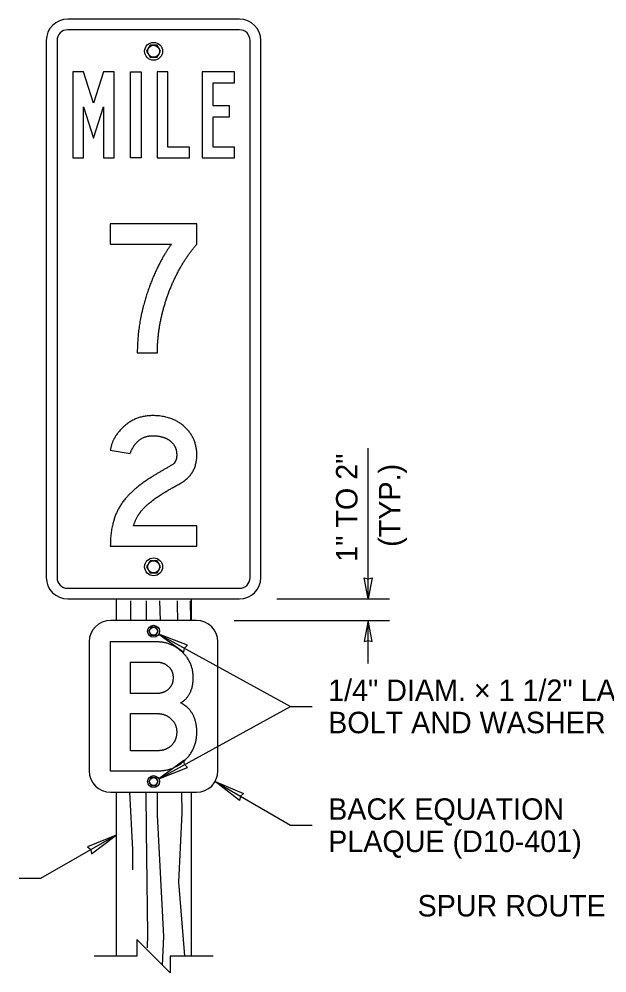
# Model space of a CAD drawing. Extents: x 99862 to 103151, y 100000 to 102076.
# Drawn here: x 101511 to 101950, y 100780 to 101491 of the extents above; entities that cross this region are included whole.
import ezdxf

# ---------------------------------------------------------------- set-up
doc = ezdxf.new("R2010")
doc.units = 0
for name, color, linetype in [('Level 11', 7, 'Continuous'), ('Level 15', 7, 'Continuous'), ('Level 2', 7, 'Continuous'), ('Level 20', 7, 'Continuous')]:
    doc.layers.add(name, color=color, linetype=linetype)

msp = doc.modelspace()

# ---------------------------------------------------------------- linework, layer by layer
at = {"layer": 'Level 11'}
for points in [[(101594.56, 101042.64), (101594.67, 101057.15)], [(101606.41, 101042.64), (101606.25, 101057.15)], [(101616.72, 101042.64), (101616.2, 101057.15)], [(101629.79, 101042.64), (101629.53, 101054.59), (101629.5, 101057.15)], [(101639.38, 101042.64), (101639.24, 101057.15)], [(101596.08, 100856.93), (101596.2, 100872.08), (101593.93, 100914.64)], [(101607.06, 100798.85), (101607.29, 100809), (101606.43, 100886.2), (101605.97, 100914.64)], [(101618.21, 100785.89), (101619.29, 100807.11), (101614.65, 100897.5), (101614.65, 100914.64)], [(101634.75, 100792.48), (101634.8, 100792.93), (101630.38, 100847.6), (101632.94, 100899.38), (101632.61, 100914.64)]]:
    msp.add_lwpolyline(points, dxfattribs=at)
at = {"layer": 'Level 15'}
for p, q in [((101771.62, 101058.64), (101771.62, 101170.99)), ((101583.62, 101058.64), (101583.62, 101042.64)), ((101639.62, 101058.64), (101639.62, 101042.64)), ((101703.62, 101058.64), (101787.62, 101058.64)), ((101671.62, 101042.64), (101787.62, 101042.64)), ((101771.62, 101010.64), (101771.62, 101042.64)), ((101615.52, 101032.5), (101713.77, 100978.64)), ((101615.52, 100924.77), (101713.77, 100978.64)), ((101713.77, 100978.64), (101729.77, 100978.64)), ((101657.47, 100922.64), (101713.77, 100890.14)), ((101583.62, 100914.64), (101583.62, 100792.48)), ((101639.62, 100914.64), (101639.62, 100792.48)), ((101713.77, 100890.14), (101729.77, 100890.14)), ((101583.62, 100882.82), (101527.33, 100850.32)), ((101527.33, 100850.32), (101511.33, 100850.32))]:
    msp.add_line(p, q, dxfattribs=at)
for points in [[(101771.62, 101058.64), (101768.54, 101074.36), (101771.62, 101073.63), (101774.7, 101074.36)], [(101771.62, 101042.64), (101768.54, 101026.91), (101771.62, 101027.64), (101774.7, 101026.91)], [(101615.52, 101032.5), (101634.1, 101018.91), (101634.61, 101022.03), (101636.97, 101024.14)], [(101615.52, 100924.77), (101636.97, 100933.13), (101634.61, 100935.24), (101634.1, 100938.37)], [(101657.48, 100922.64), (101678.74, 100913.81), (101676.33, 100911.75), (101675.75, 100908.64)], [(101583.62, 100882.82), (101562.36, 100873.99), (101564.76, 100871.93), (101565.34, 100868.82)]]:
    msp.add_lwpolyline(points, close=True, dxfattribs=at)
msp.add_lwpolyline([(101656.01, 100792.48), (101624.01, 100792.48), (101624.01, 100780.09), (101599.23, 100804.87), (101599.23, 100792.48), (101567.23, 100792.48)], dxfattribs=at)
at = {"layer": 'Level 2'}
for p, q in [((101675.62, 101482.64), (101547.62, 101482.64)), ((101539.62, 101474.64), (101539.62, 101074.64)), ((101683.62, 101074.64), (101683.62, 101474.64)), ((101547.62, 101066.64), (101675.62, 101066.64))]:
    msp.add_line(p, q, dxfattribs=at)
for points in [[(101675.62, 101490.64), (101547.62, 101490.64)], [(101531.62, 101474.64), (101531.62, 101074.64)], [(101691.62, 101074.64), (101691.62, 101474.64)], [(101559.3, 101451.24), (101551.3, 101451.24), (101551.3, 101387.24), (101559.3, 101387.24), (101559.3, 101425.26)], [(101574.34, 101451.24), (101566.82, 101428), (101559.3, 101451.24)], [(101574.34, 101425.26), (101574.34, 101387.24), (101582.34, 101387.24), (101582.34, 101451.24), (101574.34, 101451.24)], [(101638.34, 101395.24), (101622.34, 101395.24), (101622.34, 101451.24), (101614.34, 101451.24), (101614.34, 101387.24), (101638.34, 101387.24), (101638.34, 101395.24)], [(101559.3, 101425.26), (101566.82, 101402.03), (101574.34, 101425.26)], [(101643.87, 101323.04), (101643.87, 101338.04), (101579.37, 101338.04), (101579.37, 101323.04), (101624.97, 101323.04)], [(101599.47, 101242.04), (101614.47, 101242.04)], [(101579.37, 101169.44), (101594.07, 101167.04)], [(101643.87, 101098.04), (101643.87, 101113.04), (101596.62, 101113.04)], [(101579.37, 101098.04), (101643.87, 101098.04)], [(101547.62, 101058.64), (101675.62, 101058.64)], [(101643.62, 101042.64), (101579.62, 101042.64)], [(101563.62, 101026.64), (101563.62, 100930.64)], [(101614.47, 101026.64), (101579.37, 101026.64), (101579.37, 100930.64), (101615.07, 100930.64)], [(101659.62, 100930.64), (101659.62, 101026.64)], [(101614.47, 100988.24), (101594.37, 100988.24), (101594.37, 101011.64), (101614.47, 101011.64)], [(101615.07, 100945.64), (101594.37, 100945.64), (101594.37, 100973.24), (101615.07, 100973.24)], [(101579.62, 100914.64), (101643.62, 100914.64)]]:
    msp.add_lwpolyline(points, dxfattribs=at)
for points in [[(101614.22, 101471.14), (101609.02, 101471.14), (101606.42, 101466.64), (101609.02, 101462.14), (101614.22, 101462.14), (101616.82, 101466.64)], [(101614.22, 101471.14), (101609.02, 101471.14), (101606.42, 101466.64), (101609.02, 101462.14), (101614.22, 101462.14), (101616.82, 101466.64)], [(101594.34, 101451.24), (101602.34, 101451.24), (101602.34, 101387.24), (101594.34, 101387.24)], [(101668.25, 101425.9), (101655.94, 101425.9), (101655.94, 101443.24), (101671.94, 101443.24), (101671.94, 101451.24), (101647.94, 101451.24), (101647.94, 101387.24), (101671.94, 101387.24), (101671.94, 101395.24), (101655.94, 101395.24), (101655.94, 101417.9), (101668.25, 101417.9)], [(101614.22, 101087.14), (101609.02, 101087.14), (101606.42, 101082.64), (101609.02, 101078.14), (101614.22, 101078.14), (101616.82, 101082.64)], [(101613.35, 101037.64), (101609.89, 101037.64), (101608.16, 101034.64), (101609.89, 101031.64), (101613.35, 101031.64), (101615.08, 101034.64)], [(101613.35, 100925.64), (101609.89, 100925.64), (101608.16, 100922.64), (101609.89, 100919.64), (101613.35, 100919.64), (101615.08, 100922.64)]]:
    msp.add_lwpolyline(points, close=True, dxfattribs=at)
for centre, radius in [((101611.62, 101466.64), 6.67), ((101611.62, 101466.64), 4.5), ((101611.62, 101466.64), 4.5), ((101611.62, 101082.64), 6.67), ((101611.62, 101082.64), 4.5), ((101611.62, 101034.64), 4.44), ((101611.62, 101034.64), 3), ((101611.62, 100922.64), 4.44), ((101611.62, 100922.64), 3)]:
    msp.add_circle(centre, radius, dxfattribs=at)
for centre, radius, start, end in [((101547.62, 101474.64), 16, 90, 180), ((101675.62, 101474.64), 16, 360, 90), ((101547.62, 101474.64), 8, 90, 180), ((101675.62, 101474.64), 8, 0, 90), ((101547.62, 101074.64), 16, 180, 270), ((101547.62, 101074.64), 8, 180, 270), ((101675.62, 101074.64), 8, 270, 0), ((101675.62, 101074.64), 16, 270, 0), ((101579.62, 101026.64), 16, 90, 180), ((101643.62, 101026.64), 16, 360, 90), ((101579.62, 100930.64), 16, 180, 270), ((101643.62, 100930.64), 16, 270, 0)]:
    msp.add_arc(centre, radius, start, end, dxfattribs=at)
for points in [[(101624.97, 101323.04), (101619.72, 101315.99), (101614.77, 101305.94)], [(101622.27, 101285.09), (101630.07, 101306.84), (101643.87, 101323.04)], [(101614.77, 101305.94), (101608.17, 101292.44), (101604.27, 101277.89)], [(101614.47, 101242.04), (101614.47, 101263.34), (101622.27, 101285.09)], [(101604.27, 101277.89), (101599.47, 101259.89), (101599.47, 101242.04)], [(101610.87, 101195.24), (101597.97, 101195.24), (101588.67, 101186.39)], [(101635.77, 101185.94), (101626.62, 101195.24), (101610.87, 101195.24)], [(101588.67, 101186.39), (101580.72, 101178.74), (101579.37, 101169.44)], [(101643.87, 101165.84), (101643.87, 101177.69), (101635.77, 101185.94)], [(101597.67, 101173.64), (101602.77, 101180.24), (101610.87, 101180.24)], [(101610.87, 101180.24), (101619.12, 101180.24), (101624, 101176.41)], [(101624, 101176.41), (101628.87, 101172.59), (101628.87, 101165.84)], [(101594.07, 101167.04), (101596.02, 101171.54), (101597.67, 101173.64)], [(101628.87, 101165.84), (101628.87, 101161.64), (101626.47, 101159.24)], [(101632.92, 101145.59), (101643.87, 101152.49), (101643.87, 101165.84)], [(101626.47, 101159.24), (101618.37, 101154.44), (101610.42, 101149.64)], [(101610.42, 101149.64), (101591.52, 101137.94), (101585.07, 101125.04)], [(101617.92, 101136.89), (101623.62, 101140.34), (101632.92, 101145.59)], [(101602.17, 101123.84), (101607.72, 101130.59), (101617.92, 101136.89)], [(101585.07, 101125.04), (101579.37, 101113.79), (101579.37, 101098.04)], [(101596.62, 101113.04), (101598.72, 101119.64), (101602.17, 101123.84)], [(101633.07, 101018.99), (101624.97, 101026.64), (101614.47, 101026.64)], [(101641.17, 100999.94), (101641.17, 101011.34), (101633.07, 101018.99)], [(101614.47, 101011.64), (101618.37, 101011.64), (101621.82, 101009.09)], [(101621.82, 101009.09), (101626.17, 101005.79), (101626.17, 100999.94)], [(101626.17, 100999.94), (101626.17, 100993.94), (101621.67, 100990.64)], [(101634.87, 100983.44), (101641.17, 100989.44), (101641.17, 100999.94)], [(101621.67, 100990.64), (101618.37, 100988.24), (101614.47, 100988.24)], [(101631.87, 100981.34), (101633.82, 100982.54), (101634.87, 100983.44)], [(101637.87, 100976.84), (101635.92, 100978.94), (101631.87, 100981.34)], [(101643.87, 100959.44), (101643.87, 100970.09), (101637.87, 100976.84)], [(101615.07, 100973.24), (101620.32, 100973.24), (101624.6, 100969.41)], [(101624.6, 100969.41), (101628.87, 100965.59), (101628.87, 100959.44)], [(101628.87, 100959.44), (101628.87, 100952.99), (101624.37, 100949.09)], [(101635.4, 100938.96), (101643.87, 100947.29), (101643.87, 100959.44)], [(101624.37, 100949.09), (101620.47, 100945.64), (101615.07, 100945.64)], [(101615.07, 100930.64), (101626.92, 100930.64), (101635.4, 100938.96)]]:
    msp.add_open_spline(points, degree=2, dxfattribs=at)

# ---------------------------------------------------------------- texts
at = {"layer": 'Level 20'}
for s, p in [('1" TO 2"', (101763.62, 101086.37)), ('(TYP.)', (101795.62, 101097.48))]:
    msp.add_text(s, height=16, rotation=90, dxfattribs=at).set_placement(p)
for s, p in [('1/4" DIAM. × 1 1/2" LAG', (101741.77, 100982.64)), ('BOLT AND WASHER', (101741.77, 100958.64)), ('BACK EQUATION', (101741.77, 100894.14)), ('PLAQUE (D10-401)', (101741.77, 100870.14)), ('SPUR ROUTE PLAQUE', (101808.43, 100822.14))]:
    msp.add_text(s, height=16, dxfattribs=at).set_placement(p)

doc.saveas('drawing.dxf')
